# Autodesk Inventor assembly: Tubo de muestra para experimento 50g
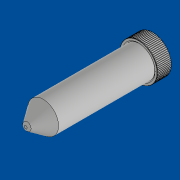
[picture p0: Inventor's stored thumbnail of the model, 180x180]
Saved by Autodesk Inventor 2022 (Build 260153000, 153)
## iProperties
Created: 2022-02
Part Number: Tubo de muestra para experimento 50g
Document SubType Name: Assembly
Designer: Juan David
Author: Juan David
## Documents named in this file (3)
- G:\Unidades compartidas\Antena para rastreo de satelites\TEMP\Proyecto globos Panama\Rios de aves_juanda\Gondola V 1.0\Estandar tubo de muestra\Tubo de muestra para experimento 50g.iam
- G:\Unidades compartidas\Antena para rastreo de satelites\TEMP\Proyecto globos Panama\Rios de aves_juanda\Gondola V 1.0\Estandar tubo de muestra\Tubo de muestra.ipt
- G:\Unidades compartidas\Antena para rastreo de satelites\TEMP\Proyecto globos Panama\Rios de aves_juanda\Gondola V 1.0\Estandar tubo de muestra\Tapa Tubodemuestra.ipt
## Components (2 placed, 2 different names)
1. Tubo de muestra:1 — Coincidencia:1, Coincidencia:2
2. Tapa Tubodemuestra:1 — Coincidencia:1, Coincidencia:2
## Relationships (2: Mate 2)
- Coincidencia:1 [Mate]: Tubo de muestra:1 ↔ Tapa Tubodemuestra:1
- Coincidencia:2 [Mate]: Tubo de muestra:1 ↔ Tapa Tubodemuestra:1
